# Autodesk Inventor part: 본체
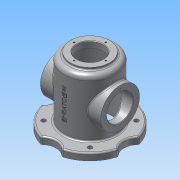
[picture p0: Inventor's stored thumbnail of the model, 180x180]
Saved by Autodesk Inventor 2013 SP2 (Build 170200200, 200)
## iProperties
Created: 2026-07
Part Number: 본체
Material: 알루미늄 6061
Document SubType Name: Modeling
Designer: a
Density: 2.71 g/cm^3
Mass: 1509.35 g
Surface Area: 1242.71 cm^2
Volume: 556.956 cm^3
Author: a
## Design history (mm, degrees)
sketch "스케치1"
  geometry: A1 r 30 centre (-100, 0) between (-79.12, -21.541) and (-79.12, 21.541); A2 r 30 centre (0, -100) between (21.541, -79.12) and (-21.541, -79.12); A3 r 30 centre (100, 0) between (79.12, 21.541) and (79.12, -21.541); A4 r 30 centre (0, 100) between (-21.541, 79.12) and (21.541, 79.12); A5 r 82 centre (0, 0) between (-79.12, -21.541) and (-21.541, -79.12); A6 r 82 centre (0, 0) between (21.541, -79.12) and (79.12, -21.541); A7 r 82 centre (0, 0) between (79.12, 21.541) and (21.541, 79.12); A8 r 82 centre (0, 0) between (-21.541, 79.12) and (-79.12, 21.541); 1 further point
  constraints: 16 point on circle, 8 centre point, 1 coincident, 1 horizontal alignment, 17 other
  dimensions: "d2" = 30 radius of A1; "d3" = 100 distance of A1.centre point (0, 0); "d6" = 360 deg dimension on point (0, 0) A1.centre (derived); "d8" = 82 radius of A6
extrude "돌출1" new body sketch "스케치1" distance "d9" = 14; taper "d10" = 0 deg
sketch "스케치3"
  geometry: C1 r 53 at (0, 0); A1 r 82 centre (0, 0) between (79.12, 21.541) and (21.541, 79.12) reference
  constraints: 1 centre point, 1 coincident
  dimensions: "d15" = 53 radius of C1
extrude "돌출2" join sketch "스케치3" distance "d16" = 118; taper "d17" = 0 deg
sketch "스케치4"
  geometry: C1 r 53 at (0, 0) reference; C2 r 40 at (0, 0)
  constraints: 1 centre point, 1 coincident
  dimensions: "d18" = 40 radius of C2
extrude "돌출3" join sketch "스케치4" distance "d19" = 5; taper "d20" = 0 deg
sketch "스케치5"
  geometry: C1 r 40 at (68, 0); 1 further point
  constraints: 1 centre point, 1 horizontal alignment
  dimensions: "d21" = 40 radius of C1; "d22" = 68 distance of point (0, 0) C1.centre
extrude "돌출4" join sketch "스케치5" stored distance "d23" = 124; taper "d24" = 0 deg
sketch "스케치6"
  geometry: C1 r 45 at (0, 0); A1 r 82 centre (0, 0) between (21.541, -79.12) and (79.12, -21.541) reference
  constraints: 1 centre point, 1 coincident
  dimensions: "d25" = 45 radius of C1
extrude "돌출5" cut sketch "스케치6" distance "d26" = 124; taper "d27" = 0 deg
sketch "스케치7"
  geometry: C1 r 45 at (0, 0) reference; C2 r 27 at (0, 0)
  constraints: 1 centre point, 1 coincident
  dimensions: "d28" = 27 radius of C2
extrude "돌출6" cut sketch "스케치7" stored distance "d29" = 124; taper "d30" = 0 deg
sketch "스케치8"
  geometry: C1 r 27 at (0, 0) reference; 1 further point
  constraints: 1 vertical alignment
  dimensions: "d31" = 32.5 distance of C1.centre point (0, 32.5)
hole "구멍1" sketch "스케치8" at (0, 32.5) diameter "d32" = 3.242; stored, may be unused: countersink angle "d36" = 90 deg, drill point angle "d38" = 118 deg; dims "d33" = 8, "d34" = 4, "d35" = 2, "d37" = 10
sketch "스케치9"
  geometry: C1 r 40 at (0, 0) reference; C2 r 27 at (0, 0); 1 further point
  constraints: 1 centre point, 1 coincident
  dimensions: "d42" = 27 radius of C2
extrude "돌출7" cut sketch "스케치9" stored distance "d43" = 124; taper "d44" = 0 deg
sketch "스케치10"
  geometry: C1 r 27 at (0, 0) reference; 2 further points
  constraints: 1 vertical alignment
  dimensions: "d45" = 32.5 distance of C1.centre point (0, 32.5)
hole "구멍2" sketch "스케치10" at (0, 32.5) diameter "d46" = 3.242; stored, may be unused: countersink angle "d50" = 90 deg, drill point angle "d52" = 118 deg; dims "d47" = 8, "d48" = 4, "d49" = 2, "d51" = 10
sketch "스케치11"
  geometry: L1 (0, 0)-(47.73, 47.73); L2 (0, 0)-(67.5, 0); C1 r 53 at (0, 0) reference; C2 r 67.5 at (0, 0); C3 r 4.5 at (47.73, 47.73)
  constraints: 4 end point, 3 coincident, 2 centre point, 1 equal length, 1 horizontal
  dimensions: "d56" = 67.5 radius of C2; "d57" = 67.5 distance of L1.start L1.end; "d58" = 45 deg angle of L2 L1; "d59" = 4.5 radius of C3
extrude "돌출8" cut sketch "스케치11" stored distance "d60" = 124; taper "d61" = 0 deg
fillet "모깎기1" dims "d65" = 10
fillet "모깎기2" dims "d66" = 3
chamfer "모따기1" distance "d67" = 1; stored, may be unused: second distance "d68" = 2, angle "d69" = 45 deg
fillet "모깎기3" dims "d70" = 3
node "작업 평면1"
sketch "스케치12"
  geometry: 2 further points
  constraints: 1 vertical alignment, 1 other
  dimensions: "d72" = 70 distance of point (0, 70) point (0, 0)
feature "엠보싱1" sketch "스케치12" dims "d4" = 40, "d73" = 0.5, "d74" = 0
node "솔리드1"
pattern_circular "원형 패턴1" dims angle "d40" = 360 deg
pattern_circular "원형 패턴2" dims angle "d54" = 360 deg
mirror "대칭1"
pattern_circular "원형 패턴3" dims angle "d63" = 360 deg
other parameters: "d0" = 82, "d71" = 81
